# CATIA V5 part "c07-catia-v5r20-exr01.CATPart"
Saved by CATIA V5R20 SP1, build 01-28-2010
Part number: Part1
Bounding box of the stored display mesh (mm): x -35 to 35, y -50 to 50, z 0 to 23
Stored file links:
  D:\v5_r20\psrt_files_downloaded\c07-catia-v5r20-prt\c07-catia-v5r20-exr01.CATPart
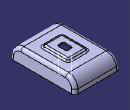
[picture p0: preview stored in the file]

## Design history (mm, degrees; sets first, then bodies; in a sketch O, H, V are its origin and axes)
Set1
  Plane1: type Offset, RefPlane face of Pad1, Offset 3, reversed
Body1 (main body)
  Sketch1 on yz-plane, origin (0, 0, 0), H (0, 1, 0), V (0, 0, 1)
    line L1 (-50, 0) -> (50, 0)
    line L2 (50, 0) -> (50, 20)
    line L3 (50, 20) -> (-50, 20)
    line L4 (-50, 20) -> (-50, 0)
    length L1 = 100
    length L2 = 20
    distance L2 V = 50
    horizontal: L1 H, L3 H
    vertical: L2 V, L4 V
    coincidence: L1 H
  Pad1: profile Sketch1, direction (1, 0, 0), length 35, mirrored extent
  Sketch2 on Plane1, origin (0, 0, 23), H (1, 0, 0), V (0, -1, 0)
    line L1 (15, 20) -> (-15, 20)
    line L2 (-15, 20) -> (-15, -20)
    line L3 (-15, -20) -> (15, -20)
    line L4 (15, -20) -> (15, 20)
    axis line L5 (-15, -20) -> (15, 20)
    length L2 = 40
    length L3 = 30
    horizontal: L1 H, L3 H
    vertical: L2 V, L4 V
    midpoint: L5 O
  Pad2: profile Sketch2, direction (0, 0, -1), up to the existing solid (limit type 2)
  Draft1: PullDir face of Pad2, Angle 5, SupportToDraft (face of Pad2; face of Pad2; face of Pad1; face of Pad1; face of Pad1; face of Pad1; face of Pad2; face of Pad2), Neutral (face of Pad2; face of Pad1)
  Fillet1: radius 15, on edge [face of Pad1 | face of Pad1] (x2)
  Fillet2: radius 5, on edge [face of Pad1 | face of Pad1] (x2)
  Fillet3: radius 3, on edge [face of Pad2 | face of Pad2] (x8)
  Fillet4: radius 3, on edge [face of Pad2 | face of Pad1]
  Shell1: IntOffset 2, Face face of Pad1, ExtOffset 0
  Sketch3 on face of Pad2, origin (0, 0, 23), H (1, 0, 0), V (0, 1, 0)
    point P1 (-5, 7.5)
    line L1 (-2, 7.5) -> (2, 7.5)
    line L2 (5, 4.5) -> (5, -4.5)
    line L3 (2, -7.5) -> (-2, -7.5)
    line L4 (-5, -4.5) -> (-5, 4.5)
    point P2 (5, 7.5)
    point P3 (5, -7.5)
    point P4 (-5, -7.5)
    axis line L5 (5, -7.5) -> (-5, 7.5)
    arc A1 centre (-2, 4.5) radius 3 from (-2, 7.5) to (-5, 4.5) ccw
    arc A2 centre (-2, -4.5) radius 3 from (-2, -7.5) to (-5, -4.5) cw
    arc A3 centre (2, -4.5) radius 3 from (2, -7.5) to (5, -4.5) ccw
    arc A4 centre (2, 4.5) radius 3 from (5, 4.5) to (2, 7.5) ccw
    radius A1 = 3
    distance P3 P4 = 10
    radius A2 = 3
    distance P2 P3 = 15
    radius A3 = 3
    radius A4 = 3
    horizontal: L1 H, L3 H
    vertical: L2 V, L4 V
    midpoint: O L5
    coincidence: L1 P1, L4 P1, L3 P4, L4 P4, L3 P3, L2 P3, L2 P2, L1 P2
    tangency: A1 L1, A1 L4, A2 L3, A2 L4, A3 L3, A3 L2, A4 L2, A4 L1
  Pocket1: profile Sketch3, direction (0, 0, -1), through (limit type 3)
